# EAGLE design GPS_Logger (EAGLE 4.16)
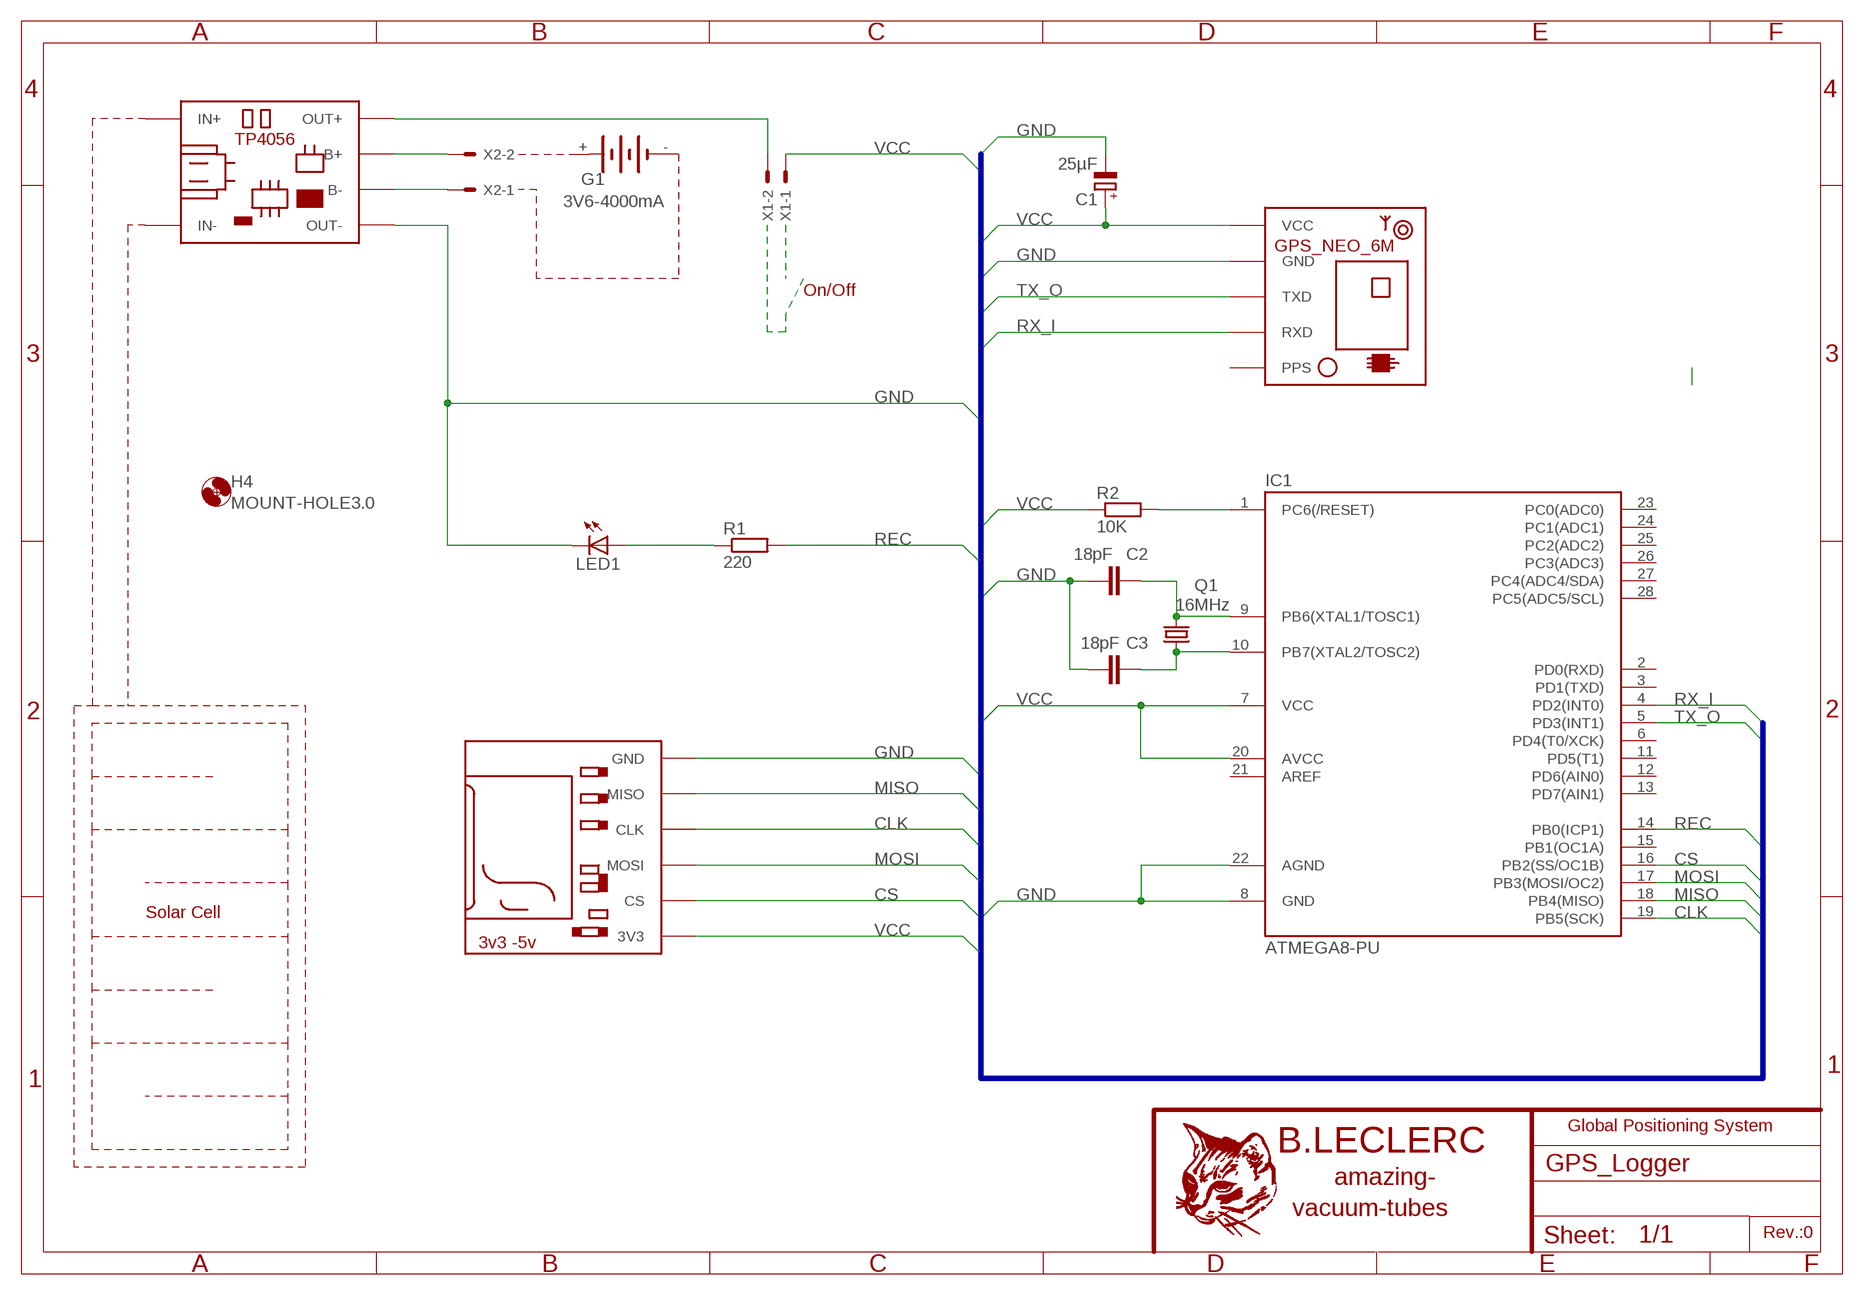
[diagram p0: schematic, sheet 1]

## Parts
C1  25µF  CPOL-EUE2.5-5  [E2,5-5]
C2  18pF  C-EUC1206K  [C1206K]
C3  18pF  C-EUC1206K  [C1206K]
G1  3V6-4000mA  3V11R  [3V11R]
H4  MOUNT-HOLE3.0  [3,0]
IC1  ATMEGA8-PU  [DIL28-3]
LED1  LEDCHIPLED_1206  [CHIPLED_1206]
Q1  16MHz  CRYTALHC49S  [HC49/S]
R1  220  R-EU_M1206  [M1206]
R2  10K  R-EU_M1206  [M1206]
U$2  CHARGEUR_ION-LI  [CHARGEUR_ION-LI]
U$3  LECTEUR_MICRO_SD  [LECTEUR_MICRO_SD]
U$4  GPS_NEO6MV2  [GPS_NEO6MV2]
X1  22-23-2021  [22-23-2021]
X2  22-23-2021  [22-23-2021]

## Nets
CLK: IC1.19(PB5(SCK)) U$3.CLK
CS: IC1.16(PB2(SS/OC1B)) U$3.CS
GND: C1.- C2.1 C3.1 IC1.8(GND) IC1.22(AGND) LED1.C U$2.OUT- U$3.GND U$4.GND
MISO: IC1.18(PB4(MISO)) U$3.MISO
MOSI: IC1.17(PB3(MOSI/OC2)) U$3.MOSI
N$1: U$2.B+ X2.2
N$4: U$2.OUT+ X1.2
N$5: U$2.B- X2.1
N$9: IC1.1(PC6(/RESET)) R2.2
N$10: LED1.A R1.1
N$11: C2.2 IC1.9(PB6(XTAL1/TOSC1)) Q1.2
N$12: C3.2 IC1.10(PB7(XTAL2/TOSC2)) Q1.1
REC: IC1.14(PB0(ICP1)) R1.2
RX_I: IC1.4(PD2(INT0)) U$4.RXD
TX_O: IC1.5(PD3(INT1)) U$4.TXD
VCC: C1.+ IC1.7(VCC) IC1.20(AVCC) R2.1 U$3.3V3 U$4.VCC X1.1
Unconnected: G1.+ G1.- IC1.2(PD0(RXD)) IC1.3(PD1(TXD)) IC1.6(PD4(T0/XCK)) IC1.11(PD5(T1)) IC1.12(PD6(AIN0)) IC1.13(PD7(AIN1)) IC1.15(PB1(OC1A)) IC1.21(AREF) IC1.23(PC0(ADC0)) IC1.24(PC1(ADC1)) IC1.25(PC2(ADC2)) IC1.26(PC3(ADC3)) IC1.27(PC4(ADC4/SDA)) IC1.28(PC5(ADC5/SCL)) U$4.PPS

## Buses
B$1

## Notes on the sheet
- On/Off
- Solar Cell
- Global Positioning System
- Rev.:0

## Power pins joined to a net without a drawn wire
IN+: U$2.IN+
IN-: U$2.IN-

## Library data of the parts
C1 = rcl:CPOL-EU: POLARIZED CAPACITOR, European symbol
C2 C3 = rcl:C-EU: CAPACITOR, European symbol
G1 = battery:3V11R: NC ACCU Varta
H4 = holes:MOUNT-HOLE: MOUNTING HOLE with drill center marker
IC1 = atmega8:ATMEGA8-PU
LED1 = led:LED: LED
Q1 = crystal:CRYTAL: CRYSTAL
R1 R2 = rcl:R-EU_: RESISTOR, European symbol
U$2 = Arduino:CHARGEUR_ION-LI
U$3 = Arduino:LECTEUR_MICRO_SD
U$4 = Arduino:GPS_NEO6MV2
X1 X2 = con-molex:22-23-2021: .100" (2.54mm) Center Header - 2 Pin

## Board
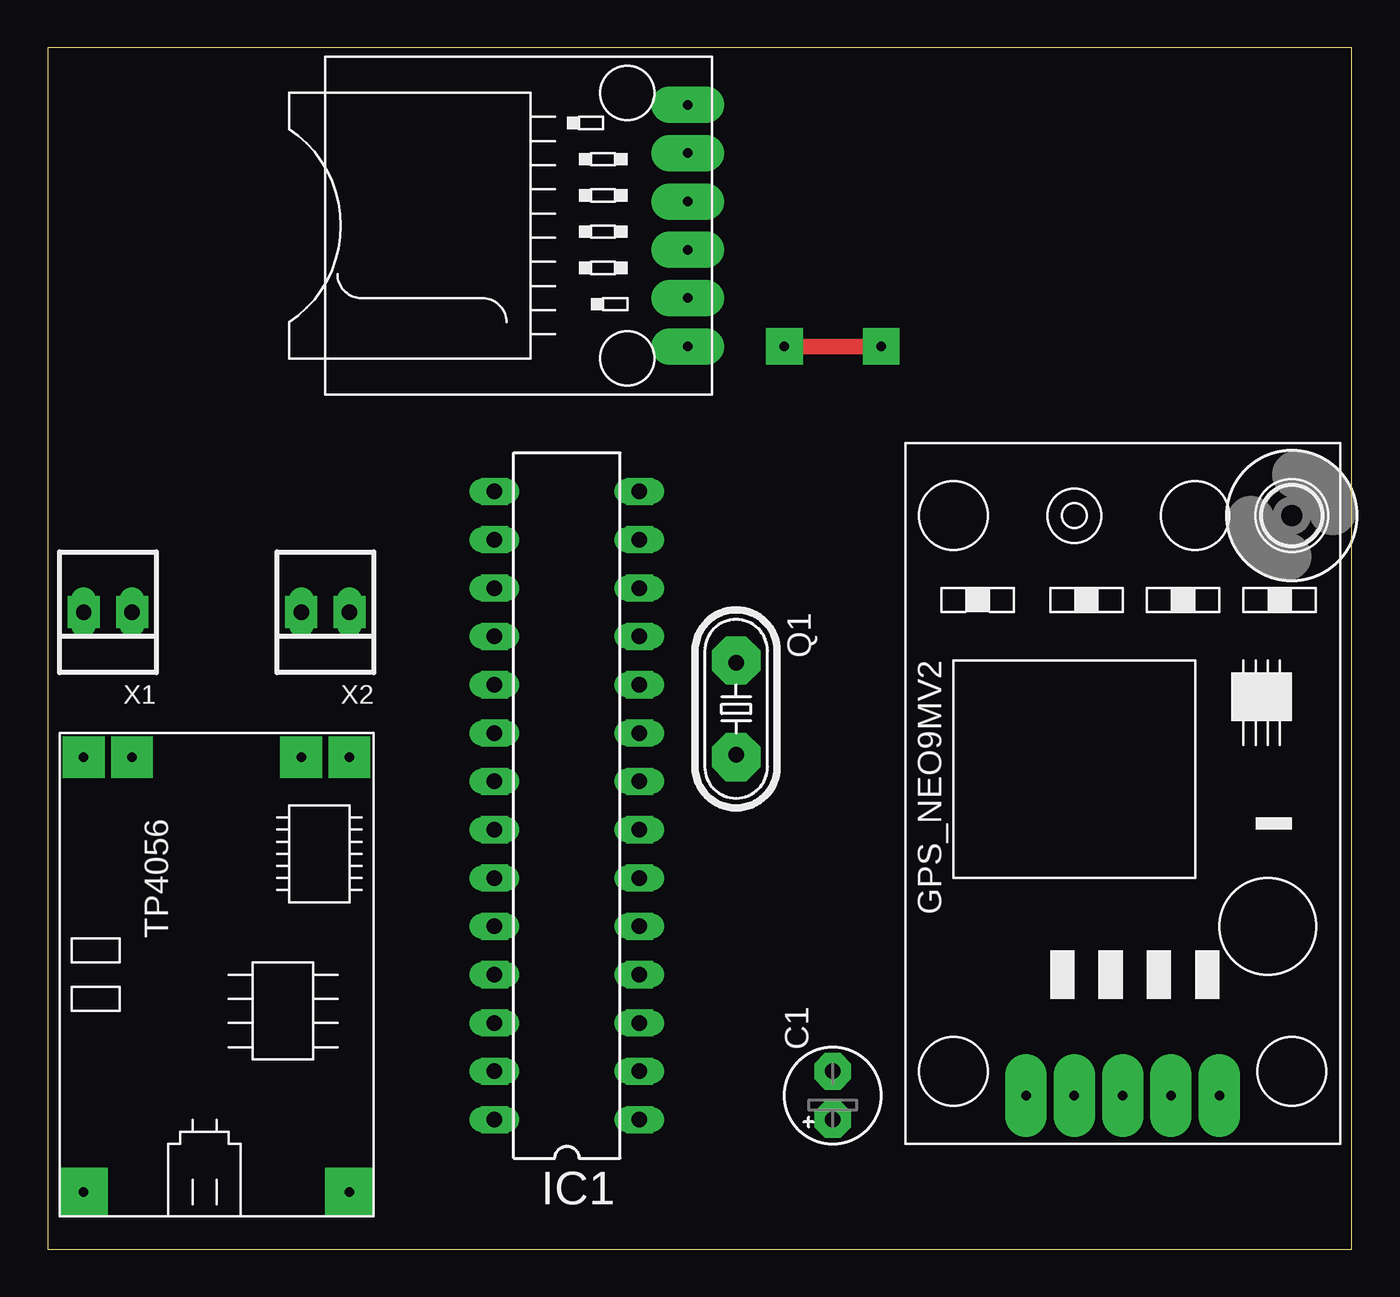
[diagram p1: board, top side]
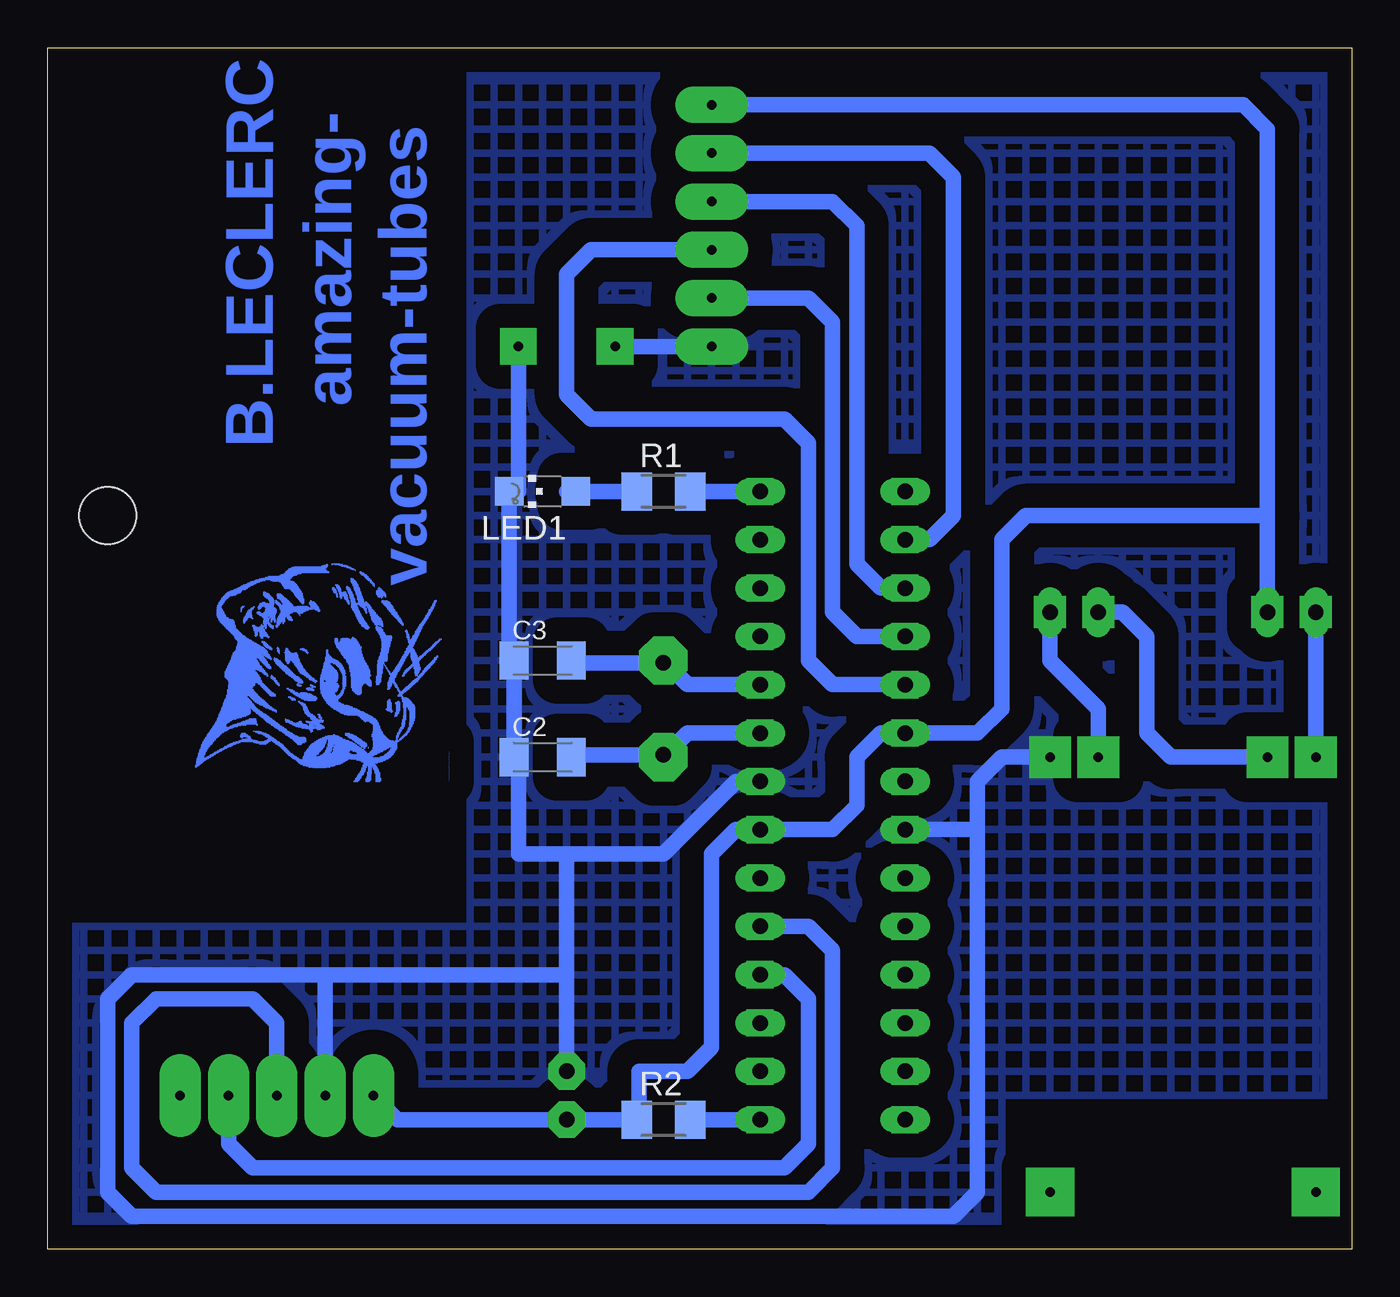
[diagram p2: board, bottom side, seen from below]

Size 68.56 x 63.17 mm. Coordinates in mm from the lower left corner, seen from the top.
Outline: 0,0 68.56,0 68.56,63.17 0,63.17 0,0
Copper layers (1*16): Top 0.035mm / dielectric 1.5mm / Bottom 0.035mm
Design rules "default": minimum track width 10mil, minimum drill 24mil, track to track 8mil, track to pad 8mil, pad to pad 8mil, via to via 8mil, smd to smd 8mil, copper to edge 40mil, drill to drill 8mil, minimum pad ring 10mil, minimum via ring 8mil, stop-mask expansion 4mil, vias tented up to drill 0mil, thermal gap 10mil

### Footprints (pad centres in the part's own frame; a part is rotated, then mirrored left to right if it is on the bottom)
E2,5-5 = drill 0.813 pad 1.6 round: + -1.27,0 | drill 0.813 pad 1.6 octagon: - 1.27,0
C1206K = smd 1.5 x 2: 1 -1.5,0; 2 1.5,0
3V11R = drill 1.118 pad 2.54 octagon: + -5.08,0; - 5.08,0
3,0 = hole 3: 0,0
DIL28-3 = drill 0.813 long: 1 -16.51,-3.81; 2 -13.97,-3.81; 3 -11.43,-3.81; 4 -8.89,-3.81; 5 -6.35,-3.81; 6 -3.81,-3.81; 7 -1.27,-3.81; 8 1.27,-3.81; 9 3.81,-3.81; 10 6.35,-3.81; 11 8.89,-3.81; 12 11.43,-3.81; 13 13.97,-3.81; 14 16.51,-3.81; 15 16.51,3.81; 16 13.97,3.81; 17 11.43,3.81; 18 8.89,3.81; 19 6.35,3.81; 20 3.81,3.81; 21 1.27,3.81; 22 -1.27,3.81; 23 -3.81,3.81; 24 -6.35,3.81; 25 -8.89,3.81; 26 -11.43,3.81; 27 -13.97,3.81; 28 -16.51,3.81
CHIPLED_1206 = smd 1.5 x 1.5: A 0,-1.75; C 0,1.75
HC49/S = drill 0.813 round: 1 -2.413,0; 2 2.413,0
M1206 = smd 1.6 x 2: 1 -1.4,0; 2 1.4,0
CHARGEUR_ION-LI = drill 0.5 pad 2.184 square: B+ 24.13,12.7; B- 24.13,3.81; OUT+ 24.13,15.24; OUT- 24.13,1.27 | drill 0.5 pad 2.54 square: IN+ 1.27,15.24; IN- 1.27,1.27
LECTEUR_MICRO_SD = drill 0.5 pad 1.93 long: 3V3 0,-6.35; CLK 0,1.27; CS 0,-3.81; GND 0,6.35; MISO 0,3.81; MOSI 0,-1.27
GPS_NEO6MV2 = drill 0.5 pad 2.184 long: GND 2.54,13.97; PPS 2.54,6.35; RXD 2.54,8.89; TXD 2.54,11.43; VCC 2.54,16.51
22-23-2021 = drill 0.813 long: 1 -1.27,0; 2 1.27,0

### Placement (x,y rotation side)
C1  41.27,8.09 90 top
C2  42.54,25.87 0 bottom
C3  42.54,30.95 0 bottom
G1  not placed on the board
H4  65.4,38.57 0 top
IC1  27.3,23.33 90 top
LED1  42.54,39.84 90 bottom
Q1  36.19,28.41 270 top
R1  36.19,39.84 0 bottom
R2  36.19,6.82 0 bottom
U$2  17.14,1.74 90 top
U$3  33.65,53.81 180 top
U$4  67.94,5.55 90 top
U$5  [CHAT1]  47.62,24.6 90 bottom
X1  3.17,33.49 180 top
X2  14.6,33.49 180 top

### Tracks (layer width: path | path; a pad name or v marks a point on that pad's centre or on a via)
CLK
  Bottom 0.813: IC1.19 27.3,29.68 28.57,30.95 28.57,42.38 29.84,43.65 40,43.65 41.27,44.92 41.27,51.27 40,52.54 U$3.CLK
CS
  Bottom 0.813: U$3.CS 22.22,57.62 20.95,56.35 20.95,38.57 22.22,37.3 IC1.16
GND  (via drill 0.5 pad 1.42, 0.5 pad 1.93)
  Top 0.813: v43.81,47.46 v38.73,47.46
  Bottom 0.813: U$2.OUT- 18.41,25.87 19.68,24.6 19.68,22.06 | 19.68,22.06 19.68,3.01 20.95,1.74 64.13,1.74 65.4,3.01 65.4,13.17 64.13,14.44 41.27,14.44 | 41.27,14.44 53.97,14.44 U$4.GND | 19.68,22.06 IC1.22 | IC1.8 32.38,24.6 36.19,20.79 41.27,20.79 | 43.81,25.87 44.04,26.1 C3.1 43.81,30.95 44.29,31.43 LED1.C 43.81,39.84 v43.81,47.46 | 41.27,20.79 43.81,20.79 43.81,25.87 | 43.81,25.87 C2.1 | 41.27,14.44 C1.- | 41.27,14.44 41.27,20.79 | v38.73,47.46 U$3.GND
  other vias: 41.27,9.36 23.49,22.06 31.11,24.6
  pour Bottom (isolate 1.27, no thermals, hatched): 0.63,8.09 0.63,62.7 46.35,62.7 46.35,16.98 67.94,16.98 67.94,0.47 18.41,0.47 18.41,8.09
MISO
  Bottom 0.813: U$3.MISO 28.57,50 27.3,48.73 27.3,33.49 26.03,32.22 IC1.18
MOSI
  Bottom 0.813: IC1.17 24.76,34.76 26.03,36.03 26.03,53.81 27.3,55.08 U$3.MOSI
N$1
  Bottom 0.813: U$2.B+ 9.52,25.87 10.79,27.14 10.79,32.22 12.06,33.49 X2.2
N$4
  Bottom 0.813: U$2.OUT+ X1.2
N$5
  Bottom 0.813: X2.1 15.87,30.95 13.33,28.41 U$2.B-
N$6  (via drill 0.5 pad 1.93)
  other vias: 38.73,47.46
N$7  (via drill 0.5 pad 1.93)
  other vias: 43.81,47.46
N$8  (via drill 0.5 pad 1.68)
  other vias: 13.33,33.49
N$9
  Bottom 0.813: IC1.1 R2.2
N$10
  Bottom 0.813: 41.27,39.84 LED1.A R1.1
N$11
  Bottom 0.813: IC1.9 34.92,27.14 36.19,25.87 Q1.2 41.14,26 41.27,25.87 C2.2
N$12
  Bottom 0.813: IC1.10 34.92,29.68 36.19,30.95 Q1.1 41.14,30.82 41.27,30.95 C3.2
N$13  (via drill 0.5 pad 1.68)
  other vias: 15.87,33.49
N$14  (via drill 0.5 pad 1.68)
  other vias: 4.44,33.49
N$15  (via drill 0.5 pad 1.68)
  other vias: 1.9,33.49
N$16  (via drill 0.5 pad 2.54)
  other vias: 36.19,30.95
N$17  (via drill 0.5 pad 2.54)
  other vias: 36.19,25.87
N$19  (via drill 0.5 pad 1.93)
  other vias: 41.27,6.82
N$20  (via drill 0.5 pad 1.42)
  other vias: 23.49,39.84
N$21  (via drill 0.5 pad 1.42)
  other vias: 23.49,37.3
N$22  (via drill 0.5 pad 1.42)
  other vias: 23.49,24.6
N$24  (via drill 0.5 pad 1.42)
  other vias: 23.49,19.52
N$25  (via drill 0.5 pad 1.42)
  other vias: 23.49,14.44
N$26  (via drill 0.5 pad 1.42)
  other vias: 23.49,9.36
N$27  (via drill 0.5 pad 1.42)
  other vias: 31.11,39.84
N$28  (via drill 0.5 pad 1.42)
  other vias: 31.11,34.76
N$29  (via drill 0.5 pad 1.42)
  other vias: 31.11,29.68
N$31  (via drill 0.5 pad 1.42)
  other vias: 31.11,16.98
N$32  (via drill 0.5 pad 1.42)
  other vias: 31.11,14.44
N$33  (via drill 0.5 pad 1.42)
  other vias: 31.11,22.06
N$34  (via drill 0.5 pad 1.42)
  other vias: 31.11,11.9
N$35  (via drill 0.5 pad 1.42)
  other vias: 31.11,9.36
N$38  (via drill 0.5 pad 1.42)
  other vias: 31.11,6.82
N$40  (via drill 0.5 pad 1.42)
  other vias: 31.11,27.14
N$41  (via drill 0.5 pad 1.42)
  other vias: 31.11,19.52
N$42  (via drill 0.5 pad 1.42)
  other vias: 31.11,32.22
N$43  (via drill 0.5 pad 1.42)
  other vias: 31.11,37.3
N$44  (via drill 0.5 pad 1.42)
  other vias: 23.49,6.82
N$45  (via drill 0.5 pad 1.42)
  other vias: 23.49,11.9
N$46  (via drill 0.5 pad 1.42)
  other vias: 23.49,16.98
N$47  (via drill 0.5 pad 1.42)
  other vias: 23.49,19.52
N$48  (via drill 0.5 pad 1.42)
  other vias: 23.49,27.14
N$49  (via drill 0.5 pad 1.42)
  other vias: 23.49,34.76
N$50  (via drill 0.5 pad 1.42)
  other vias: 23.49,32.22
N$51  (via drill 0.5 pad 1.42)
  other vias: 23.49,29.68
REC
  Bottom 0.813: 34.92,39.84 R1.2 IC1.14
RX_I
  Bottom 0.813: U$4.RXD 59.05,5.55 57.78,4.28 29.84,4.28 28.57,5.55 28.57,13.17 29.84,14.44 IC1.4
TX_O
  Bottom 0.813: U$4.TXD 56.51,11.9 57.78,13.17 62.86,13.17 64.13,11.9 64.13,4.28 62.86,3.01 28.57,3.01 27.3,4.28 27.3,15.71 28.57,16.98 IC1.5
VCC
  Bottom 0.813: R2.1 37.46,6.82 37.46,9.36 34.92,9.36 33.65,10.63 33.65,20.79 32.38,22.06 IC1.7 27.3,22.06 26.03,23.33 26.03,25.87 24.76,27.14 IC1.20 19.68,27.14 18.41,28.41 18.41,37.3 17.14,38.57 4.44,38.57 | R2.1 C1.+ 50.16,6.82 | X1.1 4.44,38.57 | 4.44,38.57 4.44,58.89 5.71,60.16 U$3.3V3 | R2.1 50.16,6.82 | 50.16,6.82 U$4.VCC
